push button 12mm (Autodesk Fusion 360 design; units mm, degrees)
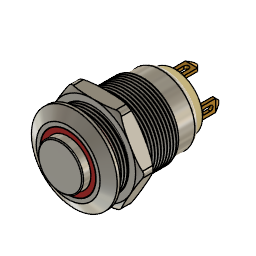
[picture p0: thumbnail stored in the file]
sketch "Sketch1" plane through (0, 0, 0) normal (0, 0, 1) x axis (1, 0, 0)
  circle C1 centre (0, 0) radius 7
  circle C2 centre (0, 0) radius 5.2
  circle C3 centre (0, 0) radius 4.5
  circle C4 centre (0, 0) radius 3.7
  point P1 (0, 0)
  point P2 (0, 0)
  coincident P1 P2
  concentric C1 C2
  concentric C2 C3
  concentric C1 C4
  dimension "d1" diameter C1 = 14
  dimension "d2" diameter C2 = 10.4
  dimension "d3" diameter C3 = 9
  dimension "d4" diameter C4 = 7.4
extrude "Extrude1" new body sketch "Sketch1" against normal blind 1.5
chamfer "Chamfer1" distance 1.8 distance 1
extrude "Extrude2" cut sketch "Sketch1" profile of C3 C4 against normal blind 1.5
extrude "Extrude3" add sketch "Sketch1" profile of C4 along normal blind 1.3
extrude "Extrude4" new body sketch "Sketch1" profile of C3 C4 against normal blind 1.5
fillet "Fillet1" radius 0.15
sketch "Sketch2" plane through (0, 0, -1.5) normal (0, 0, -1) x axis (1, 0, 0)
  circle C1 centre (0, 0) radius 7
  circle C2 centre (0, 0) radius 4.5
  circle C3 centre (0, 0) radius 6
  circle C4 centre (0, 0) radius 5.55
  point P1 (0, 0)
  point P3 (0, 0)
  point P4 (0, 0)
  coincident P1 P3
  coincident P1 P4
  dimension "d17" diameter C3 = 12
  dimension "d20" diameter C4 = 11.1
extrude "Extrude5" add sketch "Sketch2" profile of C2 C3 along normal blind 14.6 (= "16.1 mm - 1.5 mm")
extrude "Extrude6" cut sketch "Sketch2" profile of C3 C4 along normal blind 0.8
extrude "Extrude7" sketch "Sketch2" profile of C3 C4 blind -4
thread "Thread1" ThreadOffset 0 ThreadLength 10
fillet "Fillet2" radius 1
extrude "Extrude8" sketch "Sketch2" profile of C2 blind 1.3 second side blind 1
sketch "Sketch3" plane through (0, 0, -17.4) normal (0, 0, -1) x axis (1, 0, 0)
  line L1 (0, 4.5) -> (0, 0)
  line L2 (4.5, 0) -> (0, 0)
  line L3 (3.182, 3.182) -> (0, 0)
  line L4 (-1, 3.8) -> (1, 3.8)
  line L5 (-1, 3.3) -> (-1, 3.8)
  line L6 (1, 3.3) -> (-1, 3.3)
  line L7 (1, 3.8) -> (1, 3.3)
  line L8 (-1, 3.3) -> (1, 3.8)
  line L9 (1, 3.3) -> (-1, 3.8)
  line L10 (3.95, -1) -> (3.45, -1)
  line L11 (3.95, 1) -> (3.95, -1)
  line L12 (3.45, 1) -> (3.95, 1)
  line L13 (3.45, -1) -> (3.45, 1)
  line L14 (3.95, 1) -> (3.45, -1)
  line L15 (3.45, 1) -> (3.95, -1)
  line L16 (1, -3.8) -> (-1, -3.8)
  line L17 (1, -3.3) -> (1, -3.8)
  line L18 (-1, -3.8) -> (-1, -3.3)
  line L19 (-1, -3.3) -> (1, -3.3)
  line L20 (-3.95, -1) -> (-3.95, 1)
  line L21 (-3.45, -1) -> (-3.95, -1)
  line L22 (-3.95, 1) -> (-3.45, 1)
  line L23 (-3.45, 1) -> (-3.45, -1)
  line L24 (-2.2, 0.95) -> (2.2, 0.95)
  line L25 (-2.2, -0.95) -> (-2.2, 0.95)
  line L26 (2.2, -0.95) -> (-2.2, -0.95)
  line L27 (2.2, 0.95) -> (2.2, -0.95)
  line L28 (-2.2, -0.95) -> (2.2, 0.95)
  line L29 (2.2, -0.95) -> (-2.2, 0.95)
  line L30 (-0.65, 1.95) -> (0.65, 1.95)
  line L31 (-0.65, 2.15) -> (-0.65, 1.95)
  line L32 (0.65, 2.15) -> (-0.65, 2.15)
  line L33 (0.65, 1.95) -> (0.65, 2.15)
  line L34 (-0.65, 2.15) -> (0.65, 1.95)
  line L35 (0.65, 2.15) -> (-0.65, 1.95)
  line L36 (0.65, -2.15) -> (-0.65, -2.15)
  line L37 (0.65, -1.95) -> (0.65, -2.15)
  line L38 (-0.65, -1.95) -> (0.65, -1.95)
  line L39 (-0.65, -2.15) -> (-0.65, -1.95)
  line L40 (0.65, -2.15) -> (-0.65, -1.95)
  line L41 (-0.65, -2.15) -> (0.65, -1.95)
  line L42 (-0.1, -1.4) -> (0.1, -1.4)
  line L43 (-0.1, -2.7) -> (-0.1, -1.4)
  line L44 (0.1, -2.7) -> (-0.1, -2.7)
  line L45 (0.1, -1.4) -> (0.1, -2.7)
  line L46 (-0.1, -2.7) -> (0.1, -1.4)
  line L47 (0.1, -2.7) -> (-0.1, -1.4)
  circle C1 centre (0, 0) radius 4.5
  circle C2 centre (2.3688, 2.3688) radius 0.65
  point P1 (0, 0)
  point P3 (0, 0)
  point P4 (0, 4.5)
  point P5 (0, 0)
  point P6 (4.5, 0)
  point P7 (0, 0)
  point P8 (3.182, 3.182)
  point P9 (2.3688, 2.3688)
  point P14 (0, 3.55)
  point P19 (3.7, 0)
  point P32 (0, 0)
  point P37 (0, 2.05)
  point P33 (0.65, 1.95)
  point P40 (0.65, -1.95)
  point P34 (-0.65, 1.95)
  point P41 (-0.65, -1.95)
  point P35 (-0.65, 2.15)
  point P38 (-0.65, -2.15)
  point P36 (0.65, 2.15)
  point P39 (0.65, -2.15)
  point P46 (0, -2.05)
  point P12 (-1, 3.3)
  point P13 (1, 3.3)
  point P11 (-1, 3.8)
  point P15 (3.45, -1)
  point P16 (3.95, -1)
  point P17 (3.95, 1)
  point P28 (2.2, 0.95)
  point P31 (2.2, -0.95)
  point P42 (0.1, -1.4)
  point P43 (-0.1, -1.4)
  point P44 (-0.1, -2.7)
  coincident P1 P3
  coincident C1 P4
  vertical L1
  coincident P1 P5
  coincident C1 P6
  perpendicular L1 L2
  coincident P1 P7
  coincident C1 P8
  coincident L3 P9
  horizontal L4
  perpendicular L4 L5
  parallel L4 L6
  parallel L5 L7
  coincident L8 P14
  coincident L9 P14
  coincident L1 P14
  horizontal L10
  perpendicular L10 L11
  parallel L10 L12
  parallel L11 L13
  coincident L14 P19
  coincident L15 P19
  coincident L2 P19
  horizontal L24
  perpendicular L24 L25
  parallel L24 L26
  parallel L25 L27
  coincident L28 P32
  coincident L29 P32
  coincident P1 P32
  horizontal L30
  perpendicular L30 L31
  parallel L30 L32
  parallel L31 L33
  coincident L34 P37
  coincident L35 P37
  coincident L1 P37
  symmetric L2 P33 P40
  symmetric L2 P34 P41
  symmetric L2 P35 P38
  symmetric L2 P36 P39
  horizontal L42
  perpendicular L42 L43
  parallel L42 L44
  parallel L43 L45
  coincident L46 P46
  coincident L47 P46
  midpoint L41 P46
  dimension "d35" angle L2 L3 = 45
  dimension "d36" diameter C2 = 1.3
  dimension "d37" = 0.5
  dimension "d38" distance P12 P13 = 2
  dimension "d39" distance P11 P12 = 0.5
  dimension "d40" distance P15 P16 = 0.5 (= "d39")
  dimension "d41" distance P16 P17 = 2 (= "d38")
  dimension "d42" distance P1 L13 = 3.45 (= "( 6.9 / 2 ) * 1 mm")
  dimension "d43" distance P1 L6 = 3.3
  dimension "d48" distance P28 P31 = 1.9
  dimension "d49" distance L25 L27 = 4.4
  dimension "d52" distance P35 P36 = 1.3
  dimension "d53" distance P34 P35 = 0.2
  dimension "d54" distance L24 L30 = 1
  dimension "d55" distance P42 P43 = 0.2 (= "d53")
  dimension "d56" distance P43 P44 = 1.3 (= "d52")
  dimension "d45" C-Pattern1-Angle = 360
  dimension "d47" C-Pattern2-Angle = 360
extrude "Extrude9" cut sketch "Sketch3" profile of L4 L5 L6 L7 L10 L11 L12 L13 L16 L17 L18 L19 L20 L21 L22 L23 against normal blind 2.3
extrude "Extrude10" add sketch "Sketch3" profile of L30 L31 L32 L33 L36 L37 L38 L39 L42 L43 L44 L45 along normal blind 0.1
extrude "Extrude11" cut sketch "Sketch3" profile of L24 L25 L26 L27 against normal blind 0.2
extrude "Extrude12" cut sketch "Sketch3" profile of C2 against normal blind 0.4
extrude "Extrude13" new body sketch "Sketch3" profile of L4 L5 L6 L7 L10 L11 L12 L13 L16 L17 L18 L19 L20 L21 L22 L23 along normal blind 3.4 and against normal blind 2.5
chamfer "Chamfer2" distance 0.2 distance 0.7
chamfer "Chamfer3" distance 0.7 distance 0.7
sketch "Sketch4" plane through (3.95, 0, 0) normal (1, 0, 0) x axis (0, 1, 0)
  line L1 (1, -20.1) -> (-1, -20.1)
  line L2 (1, -14.9) -> (1, -20.1)
  line L3 (-1, -14.9) -> (1, -14.9)
  line L4 (-1, -20.1) -> (-1, -14.9)
  line L5 (0, -14.9) -> (0, -20.1)
  line L6 (-0.4, -19.25) -> (-0.4, -18.25)
  line L7 (0.4, -18.25) -> (0.4, -19.25)
  line L8 (0, -19.25) -> (0, -18.25)
  arc A1 centre (0, -19.25) radius 0.4 clockwise from (0.4, -19.25) to (-0.4, -19.25)
  arc A2 centre (0, -18.25) radius 0.4 clockwise from (-0.4, -18.25) to (0.4, -18.25)
  point P6 (0, -20.1)
  point P7 (0, -14.9)
  point P13 (0, -19.25)
  point P12 (0, -18.25)
  midpoint L1 P6
  midpoint L3 P7
  tangent L6 A1
  tangent A1 L7
  parallel L6 L7
  tangent L7 A2
  tangent L6 A2
  coincident L5 P13
  parallel L5 L8
  dimension "d73" distance L6 L7 = 0.8
  dimension "d74" distance P12 P13 = 1
  dimension "d75" distance L1 A1 = 0.45
extrude "Extrude14" cut sketch "Sketch4" profile of L6 A1 L7 A2 along normal blind 1.6 and against normal blind 9.7
sketch "Sketch5" plane through (0, 3.8, 0) normal (0, 1, 0) x axis (-1, 0, 0)
  line L1 (1, -20.1) -> (-1, -20.1)
  line L2 (1, -14.9) -> (1, -20.1)
  line L3 (-1, -14.9) -> (1, -14.9)
  line L4 (-1, -20.1) -> (-1, -14.9)
  line L5 (0, -14.9) -> (0, -20.1)
  line L6 (0.4, -18.25) -> (0.4, -19.25)
  line L7 (-0.4, -19.25) -> (-0.4, -18.25)
  line L8 (0, -18.25) -> (0, -19.25)
  arc A1 centre (0, -18.25) radius 0.4 clockwise from (-0.4, -18.25) to (0.4, -18.25)
  arc A2 centre (0, -19.25) radius 0.4 clockwise from (0.4, -19.25) to (-0.4, -19.25)
  point P6 (0, -20.1)
  point P7 (0, -14.9)
  point P12 (0, -19.25)
  point P13 (0, -18.25)
  midpoint L1 P6
  midpoint L3 P7
  tangent L6 A1
  tangent A1 L7
  parallel L6 L7
  tangent L7 A2
  tangent L6 A2
  parallel L5 L8
  coincident L5 P12
  dimension "d80" distance L6 L7 = 0.8
  dimension "d81" distance L1 A2 = 0.45
  dimension "d82" distance P12 P13 = 1
extrude "Extrude15" cut sketch "Sketch5" profile of L6 A1 L7 A2 against normal blind 7.6
sketch "Sketch6" plane through (0, 0, 0) normal (1, 0, 0) x axis (0, 1, 0)
  dimension "d85" = 1.5
  dimension "d86" = "'12V'"
  dimension "d87" = 0.1
  dimension "d88" = 0.7
  dimension "d89" = 5
  dimension "d90" = 3.5
  dimension "d91" = 1.5
  dimension "d93" = 0.8
  dimension "d94" = 1.75
  dimension "d95" = 2.2
  dimension "d96" = 0.7 (= "d88")
offset_faces "OffsetFaces1" distance -0.05
offset_faces "OffsetFaces2" distance -0.05
sketch "Sketch7" plane through (0, 0, -1.5) normal (0, 0, -1) x axis (1, 0, 0)
  circle C1 centre (0, 0) radius 3.65
  circle C2 centre (0, 0) radius 4.55
  point P1 (0, 0)
  point P3 (0, 0)
  coincident P1 P3
  dimension "d103" diameter C2 = 9.1
extrude "Extrude16" add sketch "Sketch7" along normal blind 1
sketch "Sketch8" plane through (0, 0, 0) normal (1, 0, 0) x axis (0, 1, 0)
  line L1 (-5.55, -2.3) -> (5.55, -2.3)
  line L2 (-5.55, -1.5) -> (5.55, -1.5)
  line L3 (5.55, -2.3) -> (5.55, -1.5)
  line L4 (-5.55, -2.3) -> (-5.55, -1.5)
  line L5 (5.95, -1.9) -> (5.55, -1.9)
  circle C1 centre (5.95, -1.9) radius 0.4
  point P4 (5.55, -1.5)
  point P6 (5.55, -1.5)
  point P2 (5.55, -2.3)
  point P7 (5.55, -2.3)
  point P5 (-5.55, -1.5)
  point P8 (-5.55, -1.5)
  point P3 (-5.55, -2.3)
  point P9 (-5.55, -2.3)
  point P10 (5.55, -1.9)
  point P11 (5.95, -1.9)
  point P12 (5.95, -1.9)
  coincident P4 P6
  coincident P2 P7
  coincident P5 P8
  coincident P3 P9
  midpoint L3 P10
  perpendicular L3 L5
  coincident P11 P12
  dimension "d106" distance P10 P11 = 0.4
  dimension "d107" diameter C1 = 0.8
revolve "Revolve1" sketch "Sketch8" AlongAngle 360
sketch "Sketch9" plane through (0, 0, 0) normal (0, 0, 1) x axis (1, 0, 0)
  line L1 (-4.3301, -6.5) -> (-7.7942, -0.5)
  line L2 (3.4641, -7) -> (-3.4641, -7)
  line L3 (7.7942, -0.5) -> (4.3301, -6.5)
  line L4 (4.3301, 6.5) -> (7.7942, 0.5)
  line L5 (-3.4641, 7) -> (3.4641, 7)
  line L6 (-7.7942, 0.5) -> (-4.3301, 6.5)
  circle C1 centre (0, 0) radius 6
  arc A1 centre (-3.4641, -6) radius 1 clockwise from (-3.4641, -7) to (-4.3301, -6.5)
  arc A2 centre (3.4641, -6) radius 1 clockwise from (4.3301, -6.5) to (3.4641, -7)
  arc A3 centre (6.9282, 0) radius 1 clockwise from (7.7942, 0.5) to (7.7942, -0.5)
  arc A4 centre (3.4641, 6) radius 1 clockwise from (3.4641, 7) to (4.3301, 6.5)
  arc A5 centre (-3.4641, 6) radius 1 clockwise from (-4.3301, 6.5) to (-3.4641, 7)
  arc A6 centre (-6.9282, 0) radius 1 clockwise from (-7.7942, -0.5) to (-7.7942, 0.5)
  circle C2 centre (0, 0) radius 7
  point P1 (0, 0)
  point P2 (0, 0)
  point P3 (0, 0)
  point P22 (0, 0)
  point P17 (-4.3301, 6.5)
  point P20 (-7.7942, 0.5)
  point P11 (7.7942, 0.5)
  point P13 (4.3301, 6.5)
  coincident P1 P2
  coincident P2 P3
  horizontal L2
  tangent L1 A1
  tangent L2 A1
  tangent L2 A2
  tangent L3 A2
  equal A1 A2
  tangent L3 A3
  tangent L4 A3
  equal A1 A3
  tangent L4 A4
  tangent L5 A4
  equal A1 A4
  tangent L5 A5
  tangent L6 A5
  equal A1 A5
  tangent L1 A6
  tangent L6 A6
  equal A1 A6
  parallel L1 L4
  parallel L2 L5
  coincident P3 P22
  tangent L1 C2
  dimension "d109" diameter C1 = 12
  dimension "d110" distance L3 L6 = 14
  dimension "d111" radius A1 = 1
  dimension "d112" distance L2 L5 = 14 (= "d110")
  dimension "d113" distance L1 L4 = 14 (= "d110")
  dimension "d114" distance P2 L1 = 7
  dimension "d115" distance P2 L2 = 7 (= "d114")
  dimension "d116" distance P2 L3 = 7 (= "d115")
  dimension "d117" distance P17 P20 = 6.9282
  dimension "d118" distance P11 P13 = 6.9282
extrude "Extrude17" new body sketch "Sketch9" against normal blind 2.3
thread "Thread2" ThreadOffset 0 ThreadLength 10
sketch "Sketch10" plane through (0, 0, 0) normal (0, 1, 0) x axis (1, 0, 0)
  line L1 (-7, 0) -> (0, 0)
  line L2 (-7.7942, 0) -> (-7.9282, 0)
  line L3 (-7.9282, 0.4) -> (-7.9282, 0)
  line L4 (-7.9282, 0) -> (-7, 0)
  arc A1 centre (-6.4548, 2.5422) radius 2.6 clockwise from (-7, 0) to (-7.9282, 0.4)
  point P1 (0, 0)
  point P2 (0, 0)
  point P4 (-7.9282, 0)
  point P6 (-7.9282, 0)
  point P3 (-7, 0)
  point P7 (-7.9282, 0.4)
  coincident P1 P2
  horizontal L1
  coincident P4 P6
  perpendicular L2 L3
  dimension "d123" distance P2 P3 = 7
  dimension "d124" distance P6 P7 = 0.4
  dimension "d125" radius A1 = 2.6
revolve "Revolve2" sketch "Sketch10" AlongAngle 360
work_plane "WorkPlane1"
mirror "Mirror1" mirrorStitchTolerance 0.1
move "Move1"
move "Move2"
extrude "Extrude18" cut of existing geometry blind -0.1
component_from_bodies "Body->Comp1"
component_from_bodies "Body->Comp2"
component_from_bodies "Body->Comp3"
component_from_bodies "Body->Comp4"
component_from_bodies "Body->Comp5"
component_from_bodies "Body->Comp6"
component_from_bodies "Body->Comp7"
component_from_bodies "Body->Comp8"
component_from_bodies "Body->Comp9"
component_from_bodies "Body->Comp10"
as_built_joint "As-built1"
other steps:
base_feature "Base Feature1"
base_feature "Base Feature1"
base_feature "Base Feature1"
base_feature "Base Feature1"
base_feature "Base Feature1"
base_feature "Base Feature1"
base_feature "Base Feature1"
base_feature "Base Feature1"
base_feature "Base Feature1"
base_feature "Base Feature1"
create_component "CreateComponent1"
reparent_decal "ReparentDecal1"
remove_body "RemoveBody1"
create_component "CreateComponent2"
reparent_decal "ReparentDecal2"
remove_body "RemoveBody2"
create_component "CreateComponent3"
reparent_decal "ReparentDecal3"
remove_body "RemoveBody3"
create_component "CreateComponent4"
reparent_decal "ReparentDecal4"
remove_body "RemoveBody4"
create_component "CreateComponent5"
reparent_decal "ReparentDecal5"
remove_body "RemoveBody5"
create_component "CreateComponent6"
reparent_decal "ReparentDecal6"
remove_body "RemoveBody6"
create_component "CreateComponent7"
reparent_decal "ReparentDecal7"
remove_body "RemoveBody7"
create_component "CreateComponent8"
reparent_decal "ReparentDecal8"
remove_body "RemoveBody8"
create_component "CreateComponent9"
reparent_decal "ReparentDecal9"
remove_body "RemoveBody9"
create_component "CreateComponent10"
reparent_decal "ReparentDecal10"
remove_body "RemoveBody10"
